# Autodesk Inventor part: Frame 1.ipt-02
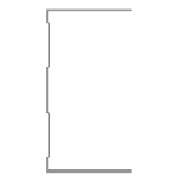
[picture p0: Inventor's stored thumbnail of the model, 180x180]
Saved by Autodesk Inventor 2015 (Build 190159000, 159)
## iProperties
IsCustomPart: 1
Created: 2015-04
Part Number: Frame 1.ipt-02
Material: Aluminum 6061
Description: Kévin Novo
Document SubType Name: Modeling
Standard: Kevin
Designer: suporte
Standards Organization: Kevin
Language: en-US
Size Designation: (Unnamed 2)
Categories: <MemberInstance><Categories><Category DisplayName="Structural Shapes" InternalName="089c4875-fa83-4c05-b084-43b9cc11f5ed" Mnemonic="GRDR"><CategoryParameter Dis
Density: 2.7 g/cm^3
Appearance: Aluminum - Flat
_CCFamilyMember: 2
_CCFamilyDisplayName: Kévin - Kévin Novo
_FrameMemberDoc: Frame Member File
_Version: 15.0.0
_GetPNFromCC: 1
G_W: 50,000 mm
G_H: 75,000 mm
G_L: 2100,000 mm
+E31B642F-311A-4DF4-B61D-D121834F4380+CUTDETAIL1: Notch
+F02AF9F0-B98F-4708-9B3F-A9D032F33C79+CUTDETAIL2: Notch
Author: suporte
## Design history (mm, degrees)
node "Start Plane"
node "End Plane"
sketch "Sketch"
  geometry: L1 (24.7, 37.5)-(24.7, 36.9); L2 (24.7, 36.9)-(-24.7, 36.9); L3 (-24.7, -36.9)-(24.7, -36.9); L4 (24.7, -36.9)-(24.7, -37.5); L5 (24.7, -37.5)-(-25.3, -37.5); L6 (-25.3, 37.5)-(24.7, 37.5); L7 (-24.7, 36.9)-(-24.7, 31.9); L8 (-24.7, 31.9)-(-23.3, 30.5); L9 (-23.3, 30.5)-(-23.3, 10.934); L10 (-23.3, 10.934)-(-24.7, 9.534); L11 (-24.7, 9.534)-(-24.7, -9.534); L12 (-24.7, -9.534)-(-23.3, -10.934); L13 (-23.3, -10.934)-(-23.3, -30.5); L14 (-23.3, -30.5)-(-24.7, -31.9); L15 (-24.7, -31.9)-(-24.7, -36.9); L16 (-25.3, -37.5)-(-25.3, -31.651); L17 (-25.3, -31.651)-(-23.9, -30.251); L18 (-23.9, -30.251)-(-23.9, -11.183); L19 (-23.9, -11.183)-(-25.3, -9.783); L20 (-25.3, -9.783)-(-25.3, 9.783); L21 (-25.3, 9.783)-(-23.9, 11.183); L22 (-23.9, 11.183)-(-23.9, 30.251); L23 (-23.9, 30.251)-(-25.3, 31.651); L24 (-25.3, 31.651)-(-25.3, 37.5); L25 (-25.3, 0)-(30.37, 0); 3 further points
  constraints: 50 end point, 10 point on line, 9 parallel, 5 perpendicular, 4 equal length, 3 midpoint, 3 vertical, 2 vertical alignment, 1 collinear, 1 horizontal, 1 horizontal alignment
  dimensions: "d3" = 0.6 distance of L1.start L1.end (= d6); "d5" = 75 distance between parallel lines of L5 L6; "d6" = 0.6 distance between parallel lines of L24 L7 (= d8); "d7" = 0.6 distance between parallel lines of L8 L23 (= d8); "d8" = 0.6 distance between parallel lines of L22 L9 (= d12); "Espessura" = 0.6 distance between parallel lines of L17 L14; "d10" = 0.6 distance between parallel lines of L13 L18 (= Espessura); "d11" = 0.6 distance between parallel lines of L12 L19 (= Espessura); "d12" = 0.6 distance between parallel lines of L21 L10 (= d11); "d13" = 5 distance of L2.end L7.end; "d15" = 135 deg angle of L9 L8; "d16" = 2 distance between parallel lines of L24 L9; "d17" = 50 distance of L6.start L1.start
extrude "Body" join sketch "Sketch" stored distance "d24" = 0.13; taper "d25" = 0 deg
node "Driven Length"
  sketch "Sketch10"
    geometry: L1 (0, 0)-(10, 0) reference
    constraints: 2 end point, 1 horizontal
  workplane "Work Plane7"
  sketch "Sketch11"
    geometry: L1 (-2, 0)-(12, 0) reference; L2 (-2, 2100)-(12, 2100) reference
    dimensions: "d27" = 2100 distance between parallel lines of L1 L2 (derived)
workplane "Work Plane8"
workplane "Work Plane9"
workplane "Work Plane10"
sketch "Sketch12"
  geometry: L1 (24.7, 37.5)-(24.7, 36.9); L2 (24.7, 36.9)-(-24.7, 36.9); L3 (-24.7, 36.9)-(-24.7, 31.9); L4 (-24.7, 31.9)-(-23.3, 30.5); L5 (-23.3, 30.5)-(-23.3, 10.934); L6 (-23.3, 10.934)-(-24.7, 9.534); L7 (-24.7, 9.534)-(-24.7, -9.534); L8 (-24.7, -9.534)-(-23.3, -10.934); L9 (-23.3, -10.934)-(-23.3, -30.5); L10 (-23.3, -30.5)-(-24.7, -31.9); L11 (-24.7, -31.9)-(-24.7, -36.9); L12 (-24.7, -36.9)-(24.7, -36.9); L13 (24.7, -36.9)-(24.7, -37.5); L14 (24.7, -37.5)-(-25.3, -37.5); L15 (-25.3, -37.5)-(-25.3, -31.651); L16 (-25.3, -31.651)-(-23.9, -30.251); L17 (-23.9, -30.251)-(-23.9, -11.183); L18 (-23.9, -11.183)-(-25.3, -9.783); L19 (-25.3, -9.783)-(-25.3, 9.783); L20 (-25.3, 9.783)-(-23.9, 11.183); L21 (-23.9, 11.183)-(-23.9, 30.251); L22 (-23.9, 30.251)-(-25.3, 31.651); L23 (-25.3, 31.651)-(-25.3, 37.5); L24 (-25.3, 37.5)-(24.7, 37.5)
  constraints: 48 end point, 10 point on line
extrude "Extrusion3" cut sketch "Sketch12" stored distance "d36" = 0.13; taper "d37" = 0 deg
workplane "Work Plane11"
workplane "Work Plane12"
workplane "Work Plane13"
sketch "Sketch13"
  geometry: L1 (24.7, 37.5)-(24.7, 36.9); L2 (24.7, 36.9)-(-24.7, 36.9); L3 (-24.7, 36.9)-(-24.7, 31.9); L4 (-24.7, 31.9)-(-23.3, 30.5); L5 (-23.3, 30.5)-(-23.3, 10.934); L6 (-23.3, 10.934)-(-24.7, 9.534); L7 (-24.7, 9.534)-(-24.7, -9.534); L8 (-24.7, -9.534)-(-23.3, -10.934); L9 (-23.3, -10.934)-(-23.3, -30.5); L10 (-23.3, -30.5)-(-24.7, -31.9); L11 (-24.7, -31.9)-(-24.7, -36.9); L12 (-24.7, -36.9)-(24.7, -36.9); L13 (24.7, -36.9)-(24.7, -37.5); L14 (24.7, -37.5)-(-25.3, -37.5); L15 (-25.3, -37.5)-(-25.3, -31.651); L16 (-25.3, -31.651)-(-23.9, -30.251); L17 (-23.9, -30.251)-(-23.9, -11.183); L18 (-23.9, -11.183)-(-25.3, -9.783); L19 (-25.3, -9.783)-(-25.3, 9.783); L20 (-25.3, 9.783)-(-23.9, 11.183); L21 (-23.9, 11.183)-(-23.9, 30.251); L22 (-23.9, 30.251)-(-25.3, 31.651); L23 (-25.3, 31.651)-(-25.3, 37.5); L24 (-25.3, 37.5)-(24.7, 37.5)
  constraints: 48 end point, 10 point on line
extrude "Extrusion4" cut sketch "Sketch13" stored distance "d38" = 0.13; taper "d39" = 0 deg
body "Solid1"
other parameters: "G_OFFSET_START" = 0 [user parameter; used in 1 equation term], "G_OFFSET_END" = 0 [user parameter; used in 1 equation term], "d22" = 0 (computed from G_OFFSET_START), "G_L" = 2100 (= d27) [user parameter], "d34" = 90 deg
